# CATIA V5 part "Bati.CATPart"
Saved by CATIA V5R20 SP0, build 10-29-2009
Part number: Bati
Publications: "Corps_bati", "raccord_bati_point_A", "raccord_bati_point_G", "raccord_bati_point_D", "Axe_pivot_bati_point_D", "Axe_pivot_bati_point_A", "Plan_ref", "Axe_pivot_bati_point_G"
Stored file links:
  C:\Users\J\IAO_2012_jgossard\Bati.CATPart
  C:\Users\J\IAO_2012_jgossard\squelette_mecanisme_presse.CATProduct

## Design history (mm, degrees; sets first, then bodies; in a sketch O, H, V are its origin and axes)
Set1
  Plane1 "Plan_ref": linked copy from another document
  Point1 "Point_A": linked copy from another document
  Point2 "Point_G": linked copy from another document
  Point3 "Point_D": linked copy from another document
  Point4 "Point_debut_bati": linked copy from another document
  Point5 "Point_fin_bati": linked copy from another document
  Point6 "Projection_point_A_bati": linked copy from another document
  Point7 "Projection_point_G_bati": linked copy from another document
  Point8 "Projection_point_D_bati": linked copy from another document
Body1 (main body)
  Line1 "Corps_bati": type PtPt, FirstPoint Point4, SecondPoint Point5
  Line2 "raccord_bati_point_A": type PtPt, FirstPoint Point6, SecondPoint Point1, Support Plane1
  Line3 "raccord_bati_point_G": type PtPt, FirstPoint Point7, SecondPoint Point2
  Line4 "raccord_bati_point_D": type PtPt, FirstPoint Point8, SecondPoint Point3
  Line5 "Axe_pivot_bati_point_D": type Normal, RefPoint Point3, RefSkin Plane1, Start 0, End 10
  Line6 "Axe_pivot_bati_point_A": type Normal, RefPoint Point1, RefSkin Plane1, Start 0, End 10
  Line7 "Axe_pivot_bati_point_G": type Normal, RefPoint Point2, RefSkin Plane1, Start 0, End 10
